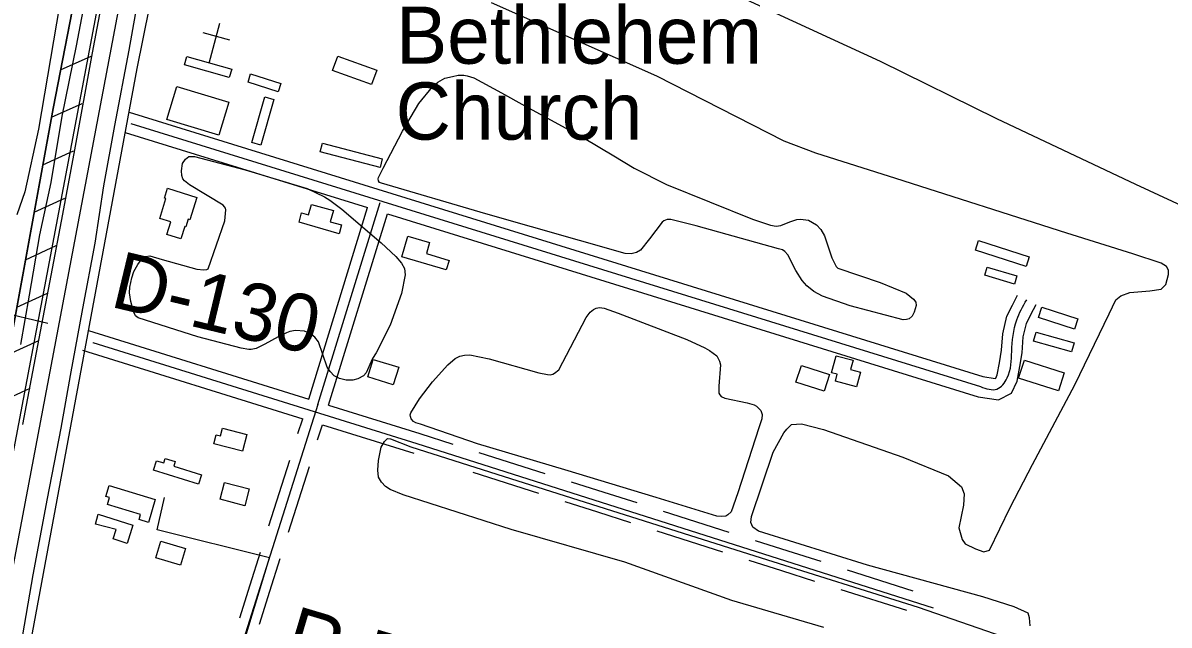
# Model space of a CAD drawing. Extents: x 3683613 to 3738215, y 469626 to 495384.
# Drawn here: x 3704159 to 3705820, y 478700 to 479573 of the extents above; entities that cross this region are included whole.
import ezdxf

# ---------------------------------------------------------------- set-up
doc = ezdxf.new("R2010")
doc.units = 0
for name, color, linetype in [('V-BLDG-OTLN', 7, 'Continuous'), ('V-DTCH-CNTR', 7, 'Continuous'), ('V-FLOD-BASE', 7, 'Continuous'), ('V-LEVE-TOET', 7, 'Continuous'), ('V-RIVR-RANG', 7, 'Continuous'), ('V-RIVR-RANG-IDEN', 7, 'Continuous'), ('V-ROAD-CNTR', 7, 'Continuous'), ('V-RRAP-FSHR', 7, 'Continuous'), ('V-SITE-OTLN', 7, 'Continuous'), ('V-SITE-OTLN-IDEN', 7, 'Continuous'), ('V-SITE-VEGE', 7, 'Continuous'), ('V-SURV-LINE', 7, 'Continuous'), ('V-TOPO-SHOR', 7, 'Continuous')]:
    doc.layers.add(name, color=color, linetype=linetype)

msp = doc.modelspace()

# ---------------------------------------------------------------- linework, layer by layer
at = {"layer": 'V-BLDG-OTLN'}
for points in [[(3704615, 479525.2), (3704671.4, 479505), (3704663.9, 479484.1), (3704607.5, 479504.3)], [(3704488.7, 479499.4), (3704532.5, 479485.6), (3704528.7, 479473.5), (3704484.9, 479487.3)], [(3704367.3, 479433.5), (3704381.6, 479481.1), (3704456.9, 479458.5), (3704442.6, 479410.8)], [(3704509.4, 479466.3), (3704522.5, 479462.5), (3704503.3, 479396.3), (3704490.2, 479400.1)], [(3704589.5, 479386.5), (3704592.8, 479399.1), (3704679.5, 479376.2), (3704676.2, 479363.5)], [(3704367.1, 479266.6), (3704372.8, 479284.8), (3704356.8, 479289.8), (3704365.7, 479318.5), (3704363.7, 479319.2), (3704368.2, 479333.5), (3704410.7, 479320.3), (3704400.7, 479287.9), (3704398.1, 479288.7), (3704394.7, 479277.7), (3704393.1, 479278.2), (3704387.5, 479260.3)], [(3704559.1, 479284.3), (3704562.4, 479297.8), (3704572.7, 479294.9), (3704577.1, 479310.2), (3704608.7, 479301.2), (3704604.1, 479285.1), (3704620.6, 479280.4), (3704616.9, 479267.6)], [(3704716.7, 479264), (3704748.1, 479254.7), (3704743.4, 479238.8), (3704776.3, 479229), (3704772.2, 479215.3), (3704708, 479234.3)], [(3705543.8, 479257.9), (3705617.3, 479234), (3705612.8, 479220.1), (3705539.3, 479244)], [(3705556.5, 479219.3), (3705599.4, 479206.4), (3705595.8, 479194.5), (3705552.9, 479207.4)], [(3705635.6, 479161.3), (3705688, 479144.2), (3705683.1, 479129.1), (3705630.7, 479146.2)], [(3705627.4, 479125), (3705682.4, 479109.1), (3705678.7, 479096.1), (3705623.6, 479111.9)], [(3705337.5, 479090.6), (3705361.9, 479084), (3705358.2, 479070.5), (3705372.7, 479066.6), (3705367.1, 479045.7), (3705336.5, 479053.9), (3705339.1, 479063.7), (3705330.9, 479065.9)], [(3704703.4, 479074), (3704695.5, 479048.4), (3704658.4, 479059.9), (3704666.2, 479085.4)], [(3705327.9, 479063.5), (3705320.1, 479039.1), (3705279.2, 479052.2), (3705287, 479076.5)], [(3705610.4, 479084.4), (3705668.1, 479065.9), (3705659.7, 479039.6), (3705602, 479058.1)], [(3704448, 478985.6), (3704483, 478976.6), (3704476.7, 478952.2), (3704435.5, 478962.8), (3704438.9, 478976), (3704445.1, 478974.4)], [(3704362.7, 478935.1), (3704364.7, 478941.6), (3704379.3, 478937.1), (3704377.2, 478930.2), (3704417.2, 478917.9), (3704413.1, 478904.3), (3704347.7, 478924.5), (3704352, 478938.4)], [(3704450.8, 478906.8), (3704486.7, 478897.4), (3704480.3, 478873.1), (3704444.4, 478882.6)], [(3704326.9, 478852.9), (3704329.1, 478860.3), (3704281, 478874.7), (3704284.1, 478885), (3704278.7, 478886.6), (3704283.5, 478902.4), (3704350.5, 478882.3), (3704340.5, 478848.8)], [(3704267.5, 478860.7), (3704318, 478844.8), (3704309.7, 478818.4), (3704289.3, 478824.8), (3704293.8, 478838.6), (3704263.8, 478846.1)], [(3704358.4, 478821.6), (3704394.4, 478810.9), (3704387.2, 478786.7), (3704351.2, 478797.3)]]:
    msp.add_lwpolyline(points, close=True, dxfattribs=at)
at = {"layer": 'V-DTCH-CNTR'}
msp.add_lwpolyline([(3704394.7, 478365.6), (3704414.3, 478464.3), (3704445.3, 478564.8), (3704490.9, 478714.8), (3704516.1, 478797.6), (3704353.3, 478838.2), (3704363.8, 478884.8)], dxfattribs=at)
at = {"layer": 'V-FLOD-BASE'}
msp.add_lwpolyline([(3704484, 480857.6), (3704470.3, 480767.7), (3704446.9, 480620.6), (3704438.1, 480557.5), (3704416.4, 480425), (3704405.8, 480355.7), (3704396, 480287.4), (3704381.3, 480194.1), (3704368.9, 480116.4), (3704356.1, 480027.9), (3704344.2, 479967.2), (3704330.2, 479903.3), (3704315.7, 479833.6), (3704309.6, 479801.7), (3704295.8, 479722), (3704274.2, 479612.2), (3704259, 479529.8), (3704233.1, 479389.2), (3704215.7, 479296), (3704198.9, 479207), (3704179.5, 479105.4), (3704158, 478991.1)], dxfattribs=at)
at = {"layer": 'V-LEVE-TOET'}
for points in [[(3704453, 480823.4), (3704442, 480749), (3704430.8, 480673.7), (3704416.4, 480579.1), (3704402.8, 480498.2), (3704388.3, 480404.7), (3704373.4, 480303.5), (3704360.1, 480217.5), (3704346.6, 480138.1), (3704335.5, 480063.8), (3704321.7, 479971), (3704304.3, 479896.2), (3704290.6, 479822.1), (3704273.4, 479744.5), (3704253.3, 479632), (3704235.9, 479540), (3704214.9, 479438), (3704199, 479342.1), (3704182.7, 479265.8), (3704167.6, 479178.6), (3704155.1, 479106.8)], [(3704527, 480810.9), (3704510.1, 480703.4), (3704493.6, 480594.1), (3704477.7, 480492.4), (3704461, 480373.9), (3704423.7, 480135.5), (3704413.8, 480049), (3704397.1, 479959.1), (3704381.1, 479868.6), (3704359, 479773.1), (3704341.9, 479691.7), (3704326.4, 479615.9), (3704312.3, 479534), (3704291.5, 479424.4), (3704275.5, 479337.1), (3704262.9, 479253.9), (3704244.7, 479159), (3704226.9, 479062.1), (3704213.4, 478985.4), (3704193.8, 478883.6), (3704173.1, 478772.8), (3704155.4, 478671.7)]]:
    msp.add_lwpolyline(points, dxfattribs=at)
at = {"layer": 'V-RIVR-RANG'}
msp.add_line((3704194.8, 479137.4), (3703124.5, 479391.1), dxfattribs=at)
at = {"layer": 'V-ROAD-CNTR'}
for p, q in [((3704557.3, 478977.7), (3704564.1, 478999.2)), ((3704585.8, 478968.6), (3704592.7, 478990.2)), ((3704592.7, 478990.2), (3704725.1, 478949.1))]:
    msp.add_line(p, q, dxfattribs=at)
for points in [[(3703726.6, 476963.3), (3703726.6, 476963.3), (3704073.6, 478169.6), (3704082.9, 478208.9), (3704324.3, 479507.4), (3704405, 479907.3), (3704509.6, 480585.2)], [(3704312.5, 479444), (3705550, 479060.5), (3705567.9, 479057.8), (3705568.8, 479058.3), (3705571.1, 479063.1), (3705574.1, 479080.1), (3705577.1, 479098.5), (3705579.1, 479122.5), (3705585, 479147.8), (3705593.1, 479163.8), (3705600.3, 479178.4)], [(3704315.2, 479427.5), (3705546.6, 479045.8)], [(3704307, 479414.3), (3704658.3, 479305.5)], [(3704573, 479027.8), (3704658.3, 479305.5)], [(3704586.3, 479020), (3704676.3, 479313.1)], [(3704601.7, 479018.9), (3704687, 479296.6)], [(3704687, 479296.6), (3705543.3, 479031.2), (3705573, 479026.8), (3705591.6, 479036.2), (3705600, 479053.9), (3705603.7, 479075.1), (3705606.9, 479094.8), (3705608.8, 479117.8), (3705613.4, 479137.5), (3705619.9, 479150.4), (3705627.2, 479165)], [(3704253.6, 479127.3), (3704573, 479027.8)], [(3704260, 479109.6), (3704260, 479109.6), (3704729.4, 478963.4)], [(3704244.7, 479098.6), (3704564.1, 478999.2)], [(3704586.3, 479020), (3704427.1, 478516.9)], [(3704601.7, 479018.9), (3704733.9, 478977.7)], [(3704734, 478977.7), (3704781.6, 478962.5)], [(3704729.4, 478963.4), (3705478.1, 478724.7)], [(3704819.7, 478950.4), (3704915, 478920)], [(3704544.8, 478938.7), (3704514.7, 478843.4)], [(3704573.4, 478929.7), (3704543.3, 478834.3)], [(3704810.6, 478921.8), (3704905.9, 478891.4)], [(3704953.1, 478907.8), (3705000.8, 478892.6)], [(3705000.8, 478892.6), (3705048.4, 478877.5)], [(3704944, 478879.3), (3704991.6, 478864.1)], [(3704991.6, 478864.1), (3705039.3, 478848.9)], [(3705086.5, 478865.3), (3705181.8, 478834.9)], [(3705077.4, 478836.7), (3705172.7, 478806.3)], [(3705219.9, 478822.8), (3705267.5, 478807.6)], [(3705267.5, 478807.6), (3705315.2, 478792.4)], [(3704502.6, 478805.2), (3704487.5, 478757.6)], [(3704531.2, 478796.2), (3704516.1, 478748.5)], [(3705210.8, 478794.2), (3705258.4, 478779)], [(3705258.4, 478779), (3705306.1, 478763.8)], [(3705353.3, 478780.2), (3705448.5, 478749.8)], [(3704487.5, 478757.6), (3704472.4, 478709.9)], [(3704516.1, 478748.5), (3704501, 478700.8)], [(3705344.2, 478751.6), (3705439.4, 478721.3)]]:
    msp.add_lwpolyline(points, dxfattribs=at)
msp.add_spline([(3705546.6, 479045.8), (3705570.5, 479042.3), (3705585.5, 479058.5), (3705592, 479096.7), (3705599.2, 479142.6), (3705613.7, 479171.7)], degree=3, dxfattribs=at)
at = {"layer": 'V-RRAP-FSHR'}
for p, q in [((3704213.1, 479505.2), (3704257.7, 479525.1)), ((3704199.8, 479436.5), (3704244.4, 479456.4)), ((3704187.3, 479367.6), (3704231.7, 479388)), ((3704174.8, 479298.8), (3704219.1, 479319.1)), ((3704162.2, 479229.9), (3704206.6, 479250.3)), ((3704149.6, 479161), (3704194, 479181.4)), ((3704137, 479092.2), (3704181.4, 479112.5)), ((3704124.5, 479023.3), (3704168.9, 479043.7))]:
    msp.add_line(p, q, dxfattribs=at)
for points in [[(3702858, 475214.9), (3703006.6, 475446.7), (3703078, 475579.2), (3703285.6, 476047.1), (3703546.8, 476749.7), (3703611.7, 476939), (3703915.1, 478011.5), (3703976.8, 478214.3), (3704202.3, 479449.5), (3704357.8, 480250.5), (3704382.9, 480399.2)], [(3704254.4, 479717.9), (3704202.3, 479449.5), (3704110.7, 478948)]]:
    msp.add_lwpolyline(points, dxfattribs=at)
at = {"layer": 'V-SITE-OTLN'}
for p, q in [((3704428.7, 479515), (3704444.2, 479572.9)), ((3704458.4, 479548.4), (3704419.7, 479558.8))]:
    msp.add_line(p, q, dxfattribs=at)
msp.add_lwpolyline([(3704396.2, 479524.6), (3704461.2, 479506.3), (3704457.7, 479494.1), (3704392.8, 479512.4)], close=True, dxfattribs=at)
at = {"layer": 'V-SITE-VEGE'}
for p, q in [((3705077.4, 479496.1), (3704837.8, 479602.5)), ((3705262.3, 479402.1), (3705077.4, 479496.1)), ((3705308, 479384.3), (3705262.3, 479402.1)), ((3705424.1, 479347.6), (3705308, 479384.3)), ((3705671.8, 479268.6), (3705424.1, 479347.6)), ((3705767.6, 479238.3), (3705671.8, 479268.6)), ((3705808.6, 479225), (3705767.6, 479238.3)), ((3705816.4, 479219.9), (3705808.6, 479225)), ((3705815.6, 479193.8), (3705819.5, 479208.5)), ((3705819.3, 479214.8), (3705816.4, 479219.9)), ((3705819.5, 479208.5), (3705819.3, 479214.8)), ((3705808.5, 479187), (3705815.6, 479193.8)), ((3705743, 479171.6), (3705750.2, 479177.7)), ((3705750.2, 479177.7), (3705763.3, 479182.5)), ((3705763.3, 479182.5), (3705792.1, 479184.9)), ((3705792.1, 479184.9), (3705808.5, 479187)), ((3705733.3, 479151.5), (3705743, 479171.6)), ((3705683.4, 479048.4), (3705733.3, 479151.5)), ((3705621.9, 478932.7), (3705683.4, 479048.4)), ((3705265.9, 478984.2), (3705272.7, 478990.7)), ((3705272.7, 478990.7), (3705287.3, 478992)), ((3705287.3, 478992), (3705319.2, 478983.7)), ((3705246.1, 478950.7), (3705261.8, 478978.9)), ((3705261.8, 478978.9), (3705265.9, 478984.2)), ((3705319.2, 478983.7), (3705434.3, 478943.5)), ((3704673.9, 478938.7), (3704678, 478958.2)), ((3704678, 478958.2), (3704682.9, 478966.3)), ((3704682.9, 478966.3), (3704687.1, 478970.4)), ((3704687.1, 478970.4), (3704691.4, 478970.1)), ((3704691.4, 478970.1), (3704720.8, 478958.6)), ((3704720.8, 478958.6), (3704845.8, 478919)), ((3705214.7, 478857.3), (3705246.1, 478950.7)), ((3705434.3, 478943.5), (3705500.1, 478916.4)), ((3704672.9, 478924.7), (3704673.9, 478938.7)), ((3704674.1, 478914.6), (3704672.9, 478924.7)), ((3705589.6, 478870.3), (3705621.9, 478932.7)), ((3704678.4, 478907.2), (3704674.1, 478914.6)), ((3704684.1, 478901.1), (3704678.4, 478907.2)), ((3704845.8, 478919), (3705002.7, 478869)), ((3705500.1, 478916.4), (3705519.2, 478900.4)), ((3704691.1, 478896.7), (3704684.1, 478901.1)), ((3704709.8, 478888.8), (3704691.1, 478896.7)), ((3705519.2, 478900.4), (3705522.9, 478890.1)), ((3705522.9, 478890.1), (3705522.3, 478873.7)), ((3704866.5, 478838.4), (3704709.8, 478888.8)), ((3705522.3, 478873.7), (3705515.3, 478840.8)), ((3705002.7, 478869), (3705228.8, 478797.6)), ((3705213.9, 478848.6), (3705214.7, 478857.3)), ((3705559.6, 478808.7), (3705589.6, 478870.3)), ((3705216.5, 478842.1), (3705213.9, 478848.6)), ((3705225, 478836), (3705216.5, 478842.1)), ((3705515.3, 478840.8), (3705520.3, 478824.2)), ((3705030.9, 478791), (3704866.5, 478838.4)), ((3705382.8, 478787), (3705225, 478836)), ((3705520.3, 478824.2), (3705524.6, 478817.7)), ((3705524.6, 478817.7), (3705539.4, 478810.7)), ((3705539.4, 478810.7), (3705551.7, 478806.4)), ((3705551.7, 478806.4), (3705559.6, 478808.7)), ((3705186.3, 478735.8), (3705030.9, 478791)), ((3705228.8, 478797.6), (3705456.5, 478725.9)), ((3705550.3, 478740.9), (3705382.8, 478787)), ((3705595.6, 478726.3), (3705550.3, 478740.9)), ((3705319.6, 478696.2), (3705186.3, 478735.8)), ((3705456.5, 478725.9), (3705591.5, 478678.8)), ((3705616, 478717), (3705595.6, 478726.3)), ((3705617.6, 478710.4), (3705616, 478717)), ((3705618.5, 478698.9), (3705617.6, 478710.4))]:
    msp.add_line(p, q, dxfattribs=at)
msp.add_lwpolyline([(3704465.9, 481177.2), (3704406.1, 480767.9), (3704350, 480389.8), (3704298.4, 480057.3), (3704233.3, 479727.1), (3704180.9, 479419.3), (3704161.5, 479328.4), (3704149.5, 479294.8)], dxfattribs=at)
for points in [[(3704678.5, 479341), (3704677.1, 479341.2), (3704675.6, 479341.9), (3704673.9, 479344.3), (3704673.5, 479347.3), (3704673.8, 479349.1), (3704681, 479362.7), (3704709, 479416.6), (3704732.7, 479456.4), (3704752.5, 479480.7), (3704760.2, 479487.5), (3704770.4, 479493.1), (3704781.3, 479495.9), (3704789.6, 479497.4), (3704797.5, 479497.4), (3704802.8, 479496.7), (3704812, 479493.6), (3704852.1, 479472), (3704886.1, 479453.3), (3704972, 479406), (3705015.3, 479380.8), (3705044.6, 479362.6), (3705091.4, 479338.9), (3705216, 479288.5), (3705242.3, 479280), (3705250.6, 479278.5), (3705257.5, 479279.5), (3705270.4, 479284.9), (3705280.3, 479288.2), (3705285.7, 479288.9), (3705297.4, 479287.1), (3705308.8, 479280.5), (3705315.5, 479273.9), (3705320.7, 479264.7), (3705331, 479232.7), (3705337.5, 479220.1), (3705339.7, 479217.8), (3705401.1, 479196.7), (3705438.8, 479181.5), (3705449.8, 479172.9), (3705453.1, 479168.3), (3705453.5, 479163.5), (3705450.6, 479153.6), (3705447.5, 479148), (3705443.3, 479144.3), (3705439.6, 479143.1), (3705434.8, 479142.8), (3705357.9, 479162.9), (3705317.6, 479177.2), (3705305, 479184), (3705294.9, 479192.1), (3705288.1, 479200), (3705279.1, 479214.5), (3705267.2, 479237.1), (3705263, 479242), (3705259.5, 479244.4), (3705254.1, 479245.9), (3705134.3, 479279), (3705097.8, 479288.2), (3705092.7, 479288.1), (3705087.9, 479286.3), (3705085.4, 479284.4), (3705067.1, 479260.1), (3705053.7, 479244), (3705047.9, 479240.4), (3705040.1, 479238.4), (3705031.6, 479238.9), (3704829.5, 479296.6)], [(3704325.7, 479145.5), (3704321.8, 479148.6), (3704319, 479155), (3704315.2, 479169.3), (3704313.2, 479181.7), (3704313.5, 479189.9), (3704316.4, 479203.4), (3704319.2, 479212.7), (3704325, 479223.1), (3704329.9, 479229.6), (3704336.4, 479234.4), (3704342.5, 479235.4), (3704360.5, 479230), (3704410.7, 479216.2), (3704420.7, 479215), (3704425.4, 479215.5), (3704427.3, 479216.6), (3704451.4, 479286.4), (3704452.9, 479302.1), (3704452.4, 479304.8), (3704450.9, 479306.8), (3704448.7, 479308.9), (3704399.9, 479338.7), (3704392.7, 479344.5), (3704390.6, 479347.3), (3704388.7, 479352.2), (3704388.2, 479359), (3704390, 479369.3), (3704394, 479375.7), (3704399, 479379.4), (3704407.4, 479379.8), (3704480.7, 479360.4), (3704570.6, 479333.4), (3704595.9, 479321), (3704603.6, 479316.2), (3704620.7, 479303.1), (3704677.9, 479254.6), (3704699, 479234.8), (3704707.5, 479224.8), (3704711.8, 479217.2), (3704712.8, 479208.1), (3704707.3, 479180.9), (3704691, 479135.1), (3704670.4, 479094.8), (3704665.4, 479086.6), (3704656.1, 479065.7), (3704652.1, 479061.5), (3704644.2, 479057.2), (3704636.7, 479055), (3704627.1, 479055.4), (3704617.4, 479057.7), (3704609.9, 479061.7), (3704603.8, 479067.7), (3704599.5, 479074.1), (3704593.4, 479092.5), (3704587, 479110.8), (3704581.8, 479117.7), (3704574.9, 479123.1), (3704566.6, 479126.3), (3704553.6, 479127.3), (3704545.4, 479125.9), (3704540.5, 479123.8), (3704528.8, 479117.8), (3704509.4, 479107.4), (3704496.8, 479101.3), (3704489.6, 479099.5), (3704485.9, 479099.5), (3704475.1, 479101.6), (3704412.2, 479118)], [(3704734.8, 478991.3), (3704728.3, 478993.2), (3704725, 478995.4), (3704721.5, 478999.2), (3704720.3, 479002.3), (3704720.1, 479005.1), (3704720.7, 479008), (3704733.4, 479028.2), (3704752.5, 479053), (3704774.5, 479077.6), (3704785, 479086.6), (3704792, 479089.9), (3704798.8, 479091.6), (3704806.4, 479091.9), (3704834.6, 479085.9), (3704906.6, 479066), (3704918.9, 479063.2), (3704923.2, 479063.1), (3704926.7, 479063.9), (3704929.4, 479065.1), (3704935.6, 479070), (3704975, 479146), (3704980.9, 479154), (3704985.6, 479157.6), (3704989.8, 479159.6), (3704994.5, 479160.5), (3705001.3, 479159.6), (3705021.4, 479152.2), (3705120.8, 479114.3), (3705147, 479102.2), (3705154, 479098.1), (3705164.3, 479090.4), (3705168.5, 479082.9), (3705169.7, 479077.4), (3705167.4, 479046.3), (3705167.5, 479036.3), (3705168.7, 479033.7), (3705170.8, 479031.3), (3705176.1, 479029), (3705208.5, 479022.3), (3705218.7, 479019.5), (3705222.2, 479017.7), (3705228.3, 479011.3), (3705230, 479005.3), (3705229.6, 478999.1), (3705225.6, 478985.9), (3705194.7, 478891.7), (3705185.1, 478864.4), (3705180.4, 478859.6), (3705177.3, 478858.1), (3705171.6, 478857.2), (3705164.6, 478858.1), (3705076.7, 478885), (3704944.3, 478925.3), (3704817.7, 478963)]]:
    msp.add_lwpolyline(points, close=True, dxfattribs=at)
at = {"layer": 'V-SURV-LINE'}
for points in [[(3704010.6, 478243.3), (3704342, 479993.7)], [(3704371.5, 479988.1), (3704040, 478237.7)]]:
    msp.add_lwpolyline(points, dxfattribs=at)
at = {"layer": 'V-TOPO-SHOR'}
msp.add_lwpolyline([(3704472.2, 479952.2), (3704596.4, 479897.8), (3704708.5, 479843.6), (3704839.6, 479781.1), (3705048.4, 479681.4), (3705225.9, 479598.8), (3705401.2, 479517.9), (3705570, 479434.6), (3705771.3, 479339.3), (3705970.5, 479247.2)], dxfattribs=at)

# ---------------------------------------------------------------- texts
at = {"layer": 'V-RIVR-RANG-IDEN'}
for s, rotation, p in [('D-130', 346.5253, (3704283, 479162.3)), ('R-72.5', 343.3927, (3704532.1, 478648.8))]:
    msp.add_text(s, height=83, rotation=rotation, dxfattribs=at).set_placement(p)
at = {"layer": 'V-SITE-OTLN-IDEN'}
for s, p in [('Bethlehem', (3704699.6, 479514.2)), ('Church', (3704698.9, 479404.1))]:
    msp.add_text(s, height=83, dxfattribs=at).set_placement(p)

doc.saveas('drawing.dxf')
